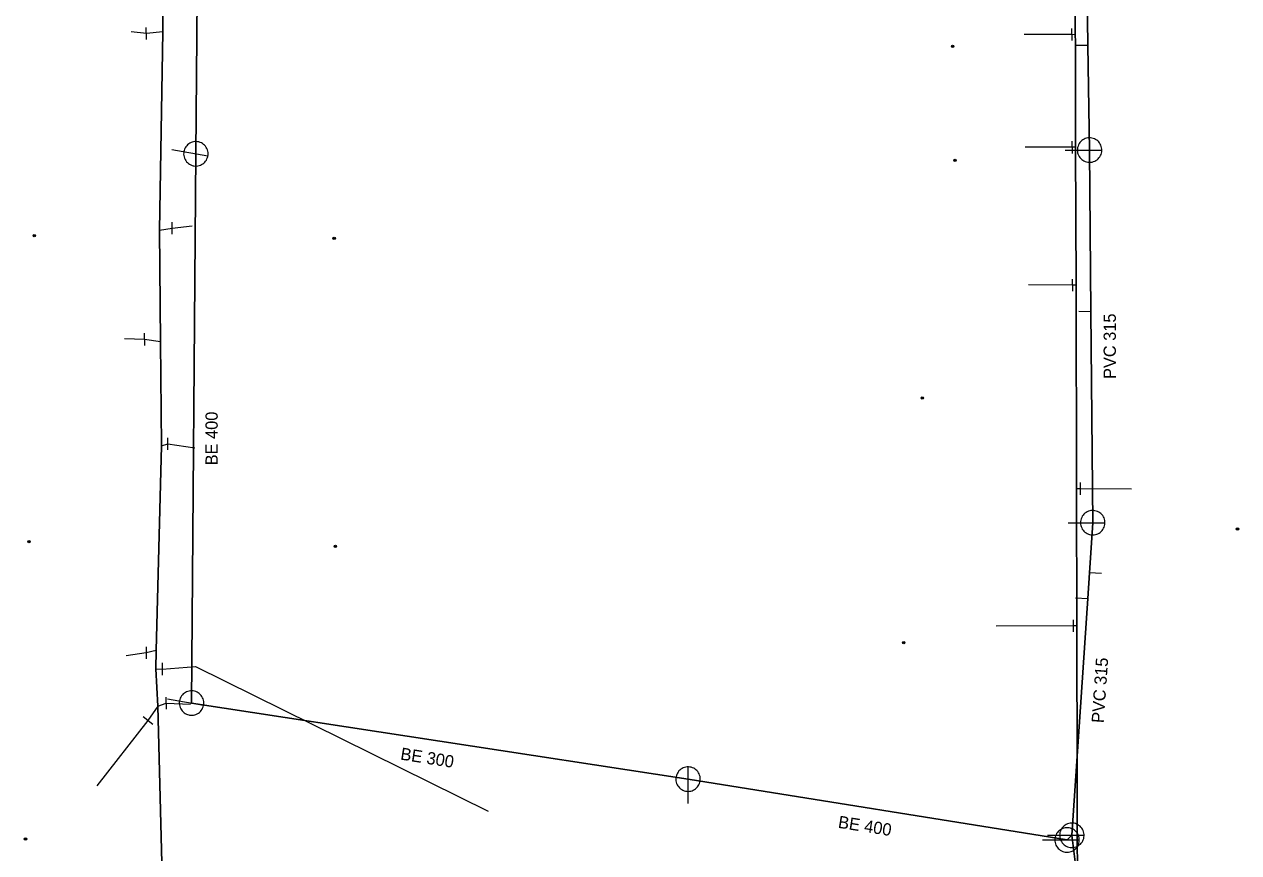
# Model space of a CAD drawing. Extents: x -783064 to -782702, y -1007904 to -1007145.
# Drawn here: x -783023 to -782923.7, y -1007741.4 to -1007673.7 of the extents above; entities that cross this region are included whole.
import ezdxf

# ---------------------------------------------------------------- set-up
doc = ezdxf.new("R2010")
doc.units = 0
doc.header["$LTSCALE"] = 0.4
doc.header["$PDMODE"] = 32
doc.header["$PDSIZE"] = 0.2
for name, color, linetype, lineweight in [('1', 7, 'Continuous', 13), ('11', 7, 'Continuous', 13), ('13', 7, 'Continuous', 13), ('14', 7, 'Continuous', 13), ('17', 7, 'Continuous', 25), ('22', 7, 'Continuous', 13), ('34', 7, 'Continuous', 13)]:
    doc.layers.add(name, color=color, linetype=linetype, lineweight=lineweight)

msp = doc.modelspace()

# ---------------------------------------------------------------- linework, layer by layer
at = {"layer": '1'}
for p in [(-782947.129, -1007675.469), (-782946.93, -1007684.789), (-783022.19, -1007690.939), (-782997.68, -1007691.159), (-782949.609, -1007704.209), (-782923.84, -1007714.929), (-783022.629, -1007715.959), (-782997.579, -1007716.349), (-782951.12, -1007724.219), (-783022.91, -1007740.259)]:
    msp.add_point(p, dxfattribs=at)
at = {"layer": '11'}
for p, q in [((-782937.064, -1007675.372), (-782936.064, -1007675.375)), ((-782936.817, -1007697.129), (-782935.817, -1007697.152)), ((-782934.945, -1007718.565), (-782935.944, -1007718.509)), ((-782937.083, -1007720.562), (-782936.083, -1007720.592))]:
    msp.add_line(p, q, dxfattribs=at)
at = {"layer": '13'}
for p, q in [((-783013.031, -1007674.425), (-783014.28, -1007674.276)), ((-783011.675, -1007674.297), (-783013.031, -1007674.425)), ((-782937.395, -1007674.509), (-782941.269, -1007674.517)), ((-782937.368, -1007683.726), (-782941.192, -1007683.713)), ((-783011.949, -1007690.495), (-783010.923, -1007690.335)), ((-783010.923, -1007690.335), (-783009.287, -1007690.134)), ((-782937.34, -1007694.992), (-782940.917, -1007694.969)), ((-783013.171, -1007699.429), (-783014.831, -1007699.375)), ((-783011.873, -1007699.631), (-783013.171, -1007699.429)), ((-783011.785, -1007708.13), (-783011.273, -1007707.961)), ((-783011.273, -1007707.961), (-783009.056, -1007708.28)), ((-782936.699, -1007711.62), (-782932.503, -1007711.648)), ((-782937.271, -1007722.838), (-782943.555, -1007722.876)), ((-783013.041, -1007725.05), (-783014.68, -1007725.303)), ((-783012.221, -1007724.861), (-783013.041, -1007725.05)), ((-783012.245, -1007726.341), (-783011.735, -1007726.374)), ((-783012.094, -1007729.406), (-783012.904, -1007730.565)), ((-783012.094, -1007729.406), (-783011.399, -1007729.163)), ((-783011.399, -1007729.163), (-783009.434, -1007729.248)), ((-783012.904, -1007730.565), (-783017.081, -1007735.926))]:
    msp.add_line(p, q, dxfattribs=at)
msp.add_lwpolyline([(-783011.735, -1007726.374), (-783009.026, -1007726.168), (-782985.094, -1007737.998)], dxfattribs=at)
at = {"layer": '14', "lineweight": 25}
for p, q in [((-783008.699, -1007648.21), (-783008.984, -1007684.256)), ((-783008.984, -1007684.256), (-783009.34, -1007729.15)), ((-783009.34, -1007729.15), (-782968.75, -1007735.37)), ((-782968.75, -1007735.37), (-782937.77, -1007740.34)), ((-782937.77, -1007740.34), (-782937.379, -1007739.96)), ((-782937.379, -1007739.96), (-782934.61, -1007761.909))]:
    msp.add_line(p, q, dxfattribs=at)
at = {"layer": '14'}
for p, q in [((-782937.095, -1007674.518), (-782937.395, -1007674.509)), ((-782937.068, -1007683.726), (-782937.368, -1007683.726)), ((-782937.04, -1007694.997), (-782937.34, -1007694.992)), ((-782936.999, -1007711.613), (-782936.699, -1007711.62)), ((-782936.971, -1007722.832), (-782937.271, -1007722.838))]:
    msp.add_line(p, q, dxfattribs=at)
at = {"layer": '14', "lineweight": 25}
for points in [[(-782936.365, -1007656.127), (-782936.192, -1007667.206), (-782936.064, -1007675.375), (-782935.93, -1007683.95)], [(-782935.93, -1007683.95), (-782935.817, -1007697.152), (-782935.67, -1007714.41)], [(-782935.67, -1007714.41), (-782935.944, -1007718.509), (-782936.083, -1007720.592), (-782937.379, -1007739.96)]]:
    msp.add_lwpolyline(points, dxfattribs=at)
at = {"layer": '17'}
for points in [[(-782936.879, -1007760.179), (-782936.971, -1007722.832), (-782936.999, -1007711.613), (-782937.04, -1007694.997), (-782937.068, -1007683.726), (-782937.09, -1007675.07), (-782937.095, -1007674.518), (-782937.094, -1007667.442), (-782937.091, -1007653.195), (-782937.09, -1007643.8), (-782937.227, -1007633.864), (-782937.409, -1007620.623), (-782937.602, -1007606.683), (-782937.658, -1007602.569), (-782938.316, -1007554.89)], [(-783009.513, -1007830.854), (-783012.094, -1007729.406), (-783012.245, -1007726.341), (-783012.221, -1007724.861), (-783011.785, -1007708.13), (-783011.873, -1007699.631), (-783011.949, -1007690.495), (-783011.675, -1007674.297), (-783011.664, -1007660.033), (-783011.55, -1007647.2), (-783011.548, -1007646.713), (-783011.508, -1007646.299)]]:
    msp.add_lwpolyline(points, dxfattribs=at)
at = {"layer": '22'}
for p, q in [((-783010.954, -1007683.908), (-783007.999, -1007684.429)), ((-782937.93, -1007683.949), (-782934.93, -1007683.95)), ((-782937.67, -1007714.409), (-782934.67, -1007714.41)), ((-783011.31, -1007728.802), (-783008.355, -1007729.323)), ((-782968.75, -1007737.37), (-782968.749, -1007734.37)), ((-782939.77, -1007740.339), (-782936.77, -1007740.34)), ((-782939.379, -1007739.959), (-782936.379, -1007739.96))]:
    msp.add_line(p, q, dxfattribs=at)
for points in [[(-783009.158, -1007685.24), (-783009.049, -1007685.253), (-783008.94, -1007685.254), (-783008.83, -1007685.243), (-783008.724, -1007685.221), (-783008.619, -1007685.187), (-783008.52, -1007685.141), (-783008.426, -1007685.085), (-783008.339, -1007685.019), (-783008.259, -1007684.944), (-783008.188, -1007684.861), (-783008.126, -1007684.77), (-783008.076, -1007684.672), (-783008.035, -1007684.571), (-783008.007, -1007684.465), (-783007.989, -1007684.357), (-783007.984, -1007684.248), (-783007.991, -1007684.138), (-783008.009, -1007684.03), (-783008.04, -1007683.925), (-783008.081, -1007683.825), (-783008.134, -1007683.728), (-783008.197, -1007683.639), (-783008.27, -1007683.556), (-783008.35, -1007683.482), (-783008.438, -1007683.417), (-783008.533, -1007683.363), (-783008.634, -1007683.319), (-783008.738, -1007683.286), (-783008.846, -1007683.265), (-783008.955, -1007683.256), (-783009.064, -1007683.258), (-783009.172, -1007683.274), (-783009.279, -1007683.3), (-783009.382, -1007683.337), (-783009.48, -1007683.387), (-783009.571, -1007683.446), (-783009.657, -1007683.515), (-783009.733, -1007683.593), (-783009.801, -1007683.679), (-783009.859, -1007683.772), (-783009.907, -1007683.87), (-783009.944, -1007683.973), (-783009.969, -1007684.081), (-783009.982, -1007684.189), (-783009.983, -1007684.299), (-783009.972, -1007684.407), (-783009.95, -1007684.515), (-783009.915, -1007684.619), (-783009.87, -1007684.719), (-783009.814, -1007684.813), (-783009.749, -1007684.9), (-783009.673, -1007684.98), (-783009.59, -1007685.051), (-783009.5, -1007685.112), (-783009.403, -1007685.163), (-783009.3, -1007685.204), (-783009.195, -1007685.233)], [(-782935.93, -1007684.949), (-782935.821, -1007684.944), (-782935.713, -1007684.926), (-782935.607, -1007684.896), (-782935.506, -1007684.856), (-782935.409, -1007684.804), (-782935.319, -1007684.742), (-782935.236, -1007684.67), (-782935.162, -1007684.59), (-782935.096, -1007684.502), (-782935.041, -1007684.408), (-782934.996, -1007684.308), (-782934.963, -1007684.203), (-782934.941, -1007684.096), (-782934.931, -1007683.987), (-782934.933, -1007683.877), (-782934.947, -1007683.769), (-782934.972, -1007683.662), (-782935.009, -1007683.559), (-782935.058, -1007683.461), (-782935.116, -1007683.369), (-782935.185, -1007683.283), (-782935.262, -1007683.206), (-782935.348, -1007683.137), (-782935.44, -1007683.078), (-782935.538, -1007683.03), (-782935.641, -1007682.993), (-782935.748, -1007682.967), (-782935.856, -1007682.953), (-782935.966, -1007682.95), (-782936.075, -1007682.96), (-782936.182, -1007682.981), (-782936.286, -1007683.015), (-782936.386, -1007683.059), (-782936.481, -1007683.114), (-782936.569, -1007683.18), (-782936.649, -1007683.254), (-782936.721, -1007683.337), (-782936.783, -1007683.427), (-782936.835, -1007683.523), (-782936.876, -1007683.625), (-782936.906, -1007683.73), (-782936.924, -1007683.838), (-782936.93, -1007683.948), (-782936.924, -1007684.057), (-782936.906, -1007684.165), (-782936.877, -1007684.27), (-782936.836, -1007684.372), (-782936.784, -1007684.469), (-782936.722, -1007684.559), (-782936.651, -1007684.642), (-782936.571, -1007684.717), (-782936.483, -1007684.782), (-782936.389, -1007684.838), (-782936.289, -1007684.882), (-782936.185, -1007684.916), (-782936.077, -1007684.938), (-782935.968, -1007684.948)], [(-782935.67, -1007715.409), (-782935.561, -1007715.404), (-782935.453, -1007715.386), (-782935.347, -1007715.356), (-782935.246, -1007715.316), (-782935.149, -1007715.264), (-782935.059, -1007715.202), (-782934.976, -1007715.13), (-782934.902, -1007715.05), (-782934.836, -1007714.962), (-782934.781, -1007714.868), (-782934.736, -1007714.768), (-782934.703, -1007714.663), (-782934.681, -1007714.556), (-782934.671, -1007714.447), (-782934.673, -1007714.337), (-782934.687, -1007714.229), (-782934.712, -1007714.122), (-782934.749, -1007714.019), (-782934.798, -1007713.921), (-782934.856, -1007713.829), (-782934.925, -1007713.743), (-782935.002, -1007713.666), (-782935.088, -1007713.597), (-782935.18, -1007713.538), (-782935.278, -1007713.49), (-782935.381, -1007713.453), (-782935.488, -1007713.427), (-782935.596, -1007713.413), (-782935.706, -1007713.41), (-782935.815, -1007713.42), (-782935.922, -1007713.441), (-782936.026, -1007713.475), (-782936.126, -1007713.519), (-782936.221, -1007713.574), (-782936.309, -1007713.64), (-782936.389, -1007713.714), (-782936.461, -1007713.797), (-782936.523, -1007713.887), (-782936.575, -1007713.983), (-782936.616, -1007714.085), (-782936.646, -1007714.19), (-782936.664, -1007714.298), (-782936.67, -1007714.408), (-782936.664, -1007714.517), (-782936.646, -1007714.625), (-782936.617, -1007714.73), (-782936.576, -1007714.832), (-782936.524, -1007714.929), (-782936.462, -1007715.019), (-782936.391, -1007715.102), (-782936.311, -1007715.177), (-782936.223, -1007715.242), (-782936.129, -1007715.298), (-782936.029, -1007715.342), (-782935.925, -1007715.376), (-782935.817, -1007715.398), (-782935.708, -1007715.408)], [(-783009.514, -1007730.134), (-783009.405, -1007730.147), (-783009.296, -1007730.148), (-783009.186, -1007730.137), (-783009.08, -1007730.115), (-783008.975, -1007730.081), (-783008.876, -1007730.035), (-783008.782, -1007729.979), (-783008.695, -1007729.913), (-783008.615, -1007729.838), (-783008.544, -1007729.755), (-783008.482, -1007729.664), (-783008.432, -1007729.566), (-783008.391, -1007729.465), (-783008.363, -1007729.359), (-783008.345, -1007729.251), (-783008.34, -1007729.142), (-783008.347, -1007729.032), (-783008.365, -1007728.924), (-783008.396, -1007728.819), (-783008.437, -1007728.719), (-783008.49, -1007728.622), (-783008.553, -1007728.533), (-783008.626, -1007728.45), (-783008.706, -1007728.376), (-783008.794, -1007728.311), (-783008.889, -1007728.257), (-783008.99, -1007728.213), (-783009.094, -1007728.18), (-783009.202, -1007728.159), (-783009.311, -1007728.15), (-783009.42, -1007728.152), (-783009.528, -1007728.168), (-783009.635, -1007728.194), (-783009.738, -1007728.231), (-783009.836, -1007728.281), (-783009.927, -1007728.34), (-783010.013, -1007728.409), (-783010.089, -1007728.487), (-783010.157, -1007728.573), (-783010.215, -1007728.666), (-783010.263, -1007728.764), (-783010.3, -1007728.867), (-783010.325, -1007728.975), (-783010.338, -1007729.083), (-783010.339, -1007729.193), (-783010.328, -1007729.301), (-783010.306, -1007729.409), (-783010.271, -1007729.513), (-783010.226, -1007729.613), (-783010.17, -1007729.707), (-783010.105, -1007729.794), (-783010.029, -1007729.874), (-783009.946, -1007729.945), (-783009.856, -1007730.006), (-783009.759, -1007730.057), (-783009.656, -1007730.098), (-783009.551, -1007730.127)], [(-782967.75, -1007735.37), (-782967.755, -1007735.261), (-782967.773, -1007735.153), (-782967.803, -1007735.047), (-782967.843, -1007734.946), (-782967.895, -1007734.849), (-782967.957, -1007734.759), (-782968.029, -1007734.676), (-782968.109, -1007734.602), (-782968.197, -1007734.536), (-782968.291, -1007734.481), (-782968.391, -1007734.436), (-782968.496, -1007734.403), (-782968.603, -1007734.381), (-782968.712, -1007734.371), (-782968.822, -1007734.373), (-782968.93, -1007734.387), (-782969.037, -1007734.412), (-782969.14, -1007734.449), (-782969.238, -1007734.498), (-782969.33, -1007734.556), (-782969.416, -1007734.625), (-782969.493, -1007734.702), (-782969.562, -1007734.788), (-782969.621, -1007734.88), (-782969.669, -1007734.978), (-782969.706, -1007735.081), (-782969.732, -1007735.188), (-782969.746, -1007735.296), (-782969.749, -1007735.406), (-782969.739, -1007735.515), (-782969.718, -1007735.622), (-782969.684, -1007735.726), (-782969.64, -1007735.826), (-782969.585, -1007735.921), (-782969.519, -1007736.009), (-782969.445, -1007736.089), (-782969.362, -1007736.161), (-782969.272, -1007736.223), (-782969.176, -1007736.275), (-782969.074, -1007736.316), (-782968.969, -1007736.346), (-782968.861, -1007736.364), (-782968.751, -1007736.37), (-782968.642, -1007736.364), (-782968.534, -1007736.346), (-782968.429, -1007736.317), (-782968.327, -1007736.276), (-782968.23, -1007736.224), (-782968.14, -1007736.162), (-782968.057, -1007736.091), (-782967.982, -1007736.011), (-782967.917, -1007735.923), (-782967.861, -1007735.829), (-782967.817, -1007735.729), (-782967.783, -1007735.625), (-782967.761, -1007735.517), (-782967.751, -1007735.408)], [(-782937.77, -1007741.339), (-782937.661, -1007741.334), (-782937.553, -1007741.316), (-782937.447, -1007741.286), (-782937.346, -1007741.246), (-782937.249, -1007741.194), (-782937.159, -1007741.132), (-782937.076, -1007741.06), (-782937.002, -1007740.98), (-782936.936, -1007740.892), (-782936.881, -1007740.798), (-782936.836, -1007740.698), (-782936.803, -1007740.593), (-782936.781, -1007740.486), (-782936.771, -1007740.377), (-782936.773, -1007740.267), (-782936.787, -1007740.159), (-782936.812, -1007740.052), (-782936.849, -1007739.949), (-782936.898, -1007739.851), (-782936.956, -1007739.759), (-782937.025, -1007739.673), (-782937.102, -1007739.596), (-782937.188, -1007739.527), (-782937.28, -1007739.468), (-782937.378, -1007739.42), (-782937.481, -1007739.383), (-782937.588, -1007739.357), (-782937.696, -1007739.343), (-782937.806, -1007739.34), (-782937.915, -1007739.35), (-782938.022, -1007739.371), (-782938.126, -1007739.405), (-782938.226, -1007739.449), (-782938.321, -1007739.504), (-782938.409, -1007739.57), (-782938.489, -1007739.644), (-782938.561, -1007739.727), (-782938.623, -1007739.817), (-782938.675, -1007739.913), (-782938.716, -1007740.015), (-782938.746, -1007740.12), (-782938.764, -1007740.228), (-782938.77, -1007740.338), (-782938.764, -1007740.447), (-782938.746, -1007740.555), (-782938.717, -1007740.66), (-782938.676, -1007740.762), (-782938.624, -1007740.859), (-782938.562, -1007740.949), (-782938.491, -1007741.032), (-782938.411, -1007741.107), (-782938.323, -1007741.172), (-782938.229, -1007741.228), (-782938.129, -1007741.272), (-782938.025, -1007741.306), (-782937.917, -1007741.328), (-782937.808, -1007741.338)], [(-782937.379, -1007740.959), (-782937.27, -1007740.954), (-782937.162, -1007740.936), (-782937.056, -1007740.906), (-782936.955, -1007740.866), (-782936.858, -1007740.814), (-782936.768, -1007740.752), (-782936.685, -1007740.68), (-782936.611, -1007740.6), (-782936.545, -1007740.512), (-782936.49, -1007740.418), (-782936.445, -1007740.318), (-782936.412, -1007740.213), (-782936.39, -1007740.106), (-782936.38, -1007739.997), (-782936.382, -1007739.887), (-782936.396, -1007739.779), (-782936.421, -1007739.672), (-782936.458, -1007739.569), (-782936.507, -1007739.471), (-782936.565, -1007739.379), (-782936.634, -1007739.293), (-782936.711, -1007739.216), (-782936.797, -1007739.147), (-782936.889, -1007739.088), (-782936.987, -1007739.04), (-782937.09, -1007739.003), (-782937.197, -1007738.977), (-782937.305, -1007738.963), (-782937.415, -1007738.96), (-782937.524, -1007738.97), (-782937.631, -1007738.991), (-782937.735, -1007739.025), (-782937.835, -1007739.069), (-782937.93, -1007739.124), (-782938.018, -1007739.19), (-782938.098, -1007739.264), (-782938.17, -1007739.347), (-782938.232, -1007739.437), (-782938.284, -1007739.533), (-782938.325, -1007739.635), (-782938.355, -1007739.74), (-782938.373, -1007739.848), (-782938.379, -1007739.958), (-782938.373, -1007740.067), (-782938.355, -1007740.175), (-782938.326, -1007740.28), (-782938.285, -1007740.382), (-782938.233, -1007740.479), (-782938.171, -1007740.569), (-782938.1, -1007740.652), (-782938.02, -1007740.727), (-782937.932, -1007740.792), (-782937.838, -1007740.848), (-782937.738, -1007740.892), (-782937.634, -1007740.926), (-782937.526, -1007740.948), (-782937.417, -1007740.958)]]:
    msp.add_lwpolyline(points, close=True, dxfattribs=at)
at = {"layer": '34'}
for p, q in [((-783013.023, -1007674.924), (-783013.037, -1007673.925)), ((-782937.402, -1007674.009), (-782937.388, -1007675.008)), ((-782937.375, -1007683.226), (-782937.361, -1007684.225)), ((-783010.915, -1007690.834), (-783010.929, -1007689.835)), ((-782937.347, -1007694.492), (-782937.333, -1007695.491)), ((-783013.163, -1007699.928), (-783013.177, -1007698.929)), ((-783011.265, -1007708.46), (-783011.279, -1007707.461)), ((-782936.706, -1007711.12), (-782936.692, -1007712.119)), ((-782937.278, -1007722.338), (-782937.264, -1007723.337)), ((-783013.048, -1007724.55), (-783013.034, -1007725.549)), ((-783011.742, -1007725.874), (-783011.728, -1007726.873)), ((-783011.391, -1007729.662), (-783011.405, -1007728.663)), ((-783013.298, -1007730.258), (-783012.509, -1007730.872))]:
    msp.add_line(p, q, dxfattribs=at)

# ---------------------------------------------------------------- texts
at = {"layer": '1'}
for s, rotation, p in [('PVC 315 ', 90, (-782933.784, -1007702.662)), ('BE 400', 90, (-783007.2, -1007709.718)), ('PVC 315 ', 86, (-782934.776, -1007730.809)), ('BE 300', 351, (-782992.311, -1007733.767)), ('BE 400', 351, (-782956.536, -1007739.339))]:
    msp.add_text(s, height=1, rotation=rotation, dxfattribs=at).set_placement(p)

doc.saveas('drawing.dxf')
